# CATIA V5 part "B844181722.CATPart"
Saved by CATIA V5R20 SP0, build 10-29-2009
Part number: B844181722
Revision: 2
Definition: design
Nomenclature: B844181722
Source: made
Description: NOT SPECIFIED
Bounding box of the stored display mesh (mm): x -16.5 to 16.5, y -16.5 to 16.5, z -17 to 22
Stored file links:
  C:\Users\Utente\Desktop\3D files B844\B844181722.CATPart
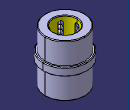
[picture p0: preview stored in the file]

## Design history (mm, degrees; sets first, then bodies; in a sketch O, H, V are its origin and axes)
Body1 "MANIFOLD_SOLID_BREP #38" (main body)
  Solid1: solid without history
Body2 "MANIFOLD_SOLID_BREP #76"
  Solid2: solid without history
Body3 "MANIFOLD_SOLID_BREP #114"
  Solid3: solid without history
Body4 "MANIFOLD_SOLID_BREP #152"
  Solid4: solid without history
Body5 "MANIFOLD_SOLID_BREP #190"
  Solid5: solid without history
Body6 "MANIFOLD_SOLID_BREP #228"
  Solid6: solid without history
Body7 "MANIFOLD_SOLID_BREP #266"
  Solid7: solid without history
Body8 "MANIFOLD_SOLID_BREP #1968"
  Solid8: solid without history
Body9 "MANIFOLD_SOLID_BREP #2006"
  Solid9: solid without history
Body10 "MANIFOLD_SOLID_BREP #2044"
  Solid10: solid without history
Body11 "MANIFOLD_SOLID_BREP #2082"
  Solid11: solid without history
Body12 "MANIFOLD_SOLID_BREP #2120"
  Solid12: solid without history
Body13 "MANIFOLD_SOLID_BREP #2158"
  Solid13: solid without history
Body14 "MANIFOLD_SOLID_BREP #2196"
  Solid14: solid without history
Body15 "MANIFOLD_SOLID_BREP #2234"
  Solid15: solid without history
Body16 "MANIFOLD_SOLID_BREP #2272"
  Solid16: solid without history
Body17 "MANIFOLD_SOLID_BREP #2310"
  Solid17: solid without history
Body18 "MANIFOLD_SOLID_BREP #2348"
  Solid18: solid without history
Body19 "MANIFOLD_SOLID_BREP #2386"
  Solid19: solid without history
Body20 "MANIFOLD_SOLID_BREP #2424"
  Solid20: solid without history
Body21 "MANIFOLD_SOLID_BREP #2462"
  Solid21: solid without history
Body22 "MANIFOLD_SOLID_BREP #2500"
  Solid22: solid without history
Body23 "MANIFOLD_SOLID_BREP #2538"
  Solid23: solid without history
Body24 "MANIFOLD_SOLID_BREP #2576"
  Solid24: solid without history
Body25 "MANIFOLD_SOLID_BREP #2614"
  Solid25: solid without history
Body26 "MANIFOLD_SOLID_BREP #2652"
  Solid26: solid without history
Body27 "MANIFOLD_SOLID_BREP #2690"
  Solid27: solid without history
Body28 "MANIFOLD_SOLID_BREP #2728"
  Solid28: solid without history
Body29 "MANIFOLD_SOLID_BREP #2766"
  Solid29: solid without history
Body30 "MANIFOLD_SOLID_BREP #2804"
  Solid30: solid without history
Body31 "MANIFOLD_SOLID_BREP #2842"
  Solid31: solid without history
Body32 "MANIFOLD_SOLID_BREP #2880"
  Solid32: solid without history
Body33 "MANIFOLD_SOLID_BREP #2918"
  Solid33: solid without history
Body34 "MANIFOLD_SOLID_BREP #2956"
  Solid34: solid without history
Body35 "MANIFOLD_SOLID_BREP #2994"
  Solid35: solid without history
Body36 "MANIFOLD_SOLID_BREP #3032"
  Solid36: solid without history
Body37 "MANIFOLD_SOLID_BREP #3070"
  Solid37: solid without history
Body38 "MANIFOLD_SOLID_BREP #3108"
  Solid38: solid without history
Body39 "MANIFOLD_SOLID_BREP #3146"
  Solid39: solid without history
Body40 "MANIFOLD_SOLID_BREP #3184"
  Solid40: solid without history
Body41 "MANIFOLD_SOLID_BREP #3222"
  Solid41: solid without history
Body42 "MANIFOLD_SOLID_BREP #3260"
  Solid42: solid without history
Body43 "MANIFOLD_SOLID_BREP #3298"
  Solid43: solid without history
Body44 "MANIFOLD_SOLID_BREP #3336"
  Solid44: solid without history
Body45 "MANIFOLD_SOLID_BREP #3374"
  Solid45: solid without history
Body46 "MANIFOLD_SOLID_BREP #3412"
  Solid46: solid without history
Body47 "MANIFOLD_SOLID_BREP #3450"
  Solid47: solid without history
Body48 "MANIFOLD_SOLID_BREP #3488"
  Solid48: solid without history
Body49 "MANIFOLD_SOLID_BREP #3526"
  Solid49: solid without history
Body50 "MANIFOLD_SOLID_BREP #3564"
  Solid50: solid without history
Body51 "MANIFOLD_SOLID_BREP #3602"
  Solid51: solid without history
Body52 "MANIFOLD_SOLID_BREP #3640"
  Solid52: solid without history
Body53 "MANIFOLD_SOLID_BREP #3678"
  Solid53: solid without history
Body54 "MANIFOLD_SOLID_BREP #3716"
  Solid54: solid without history
Body55 "MANIFOLD_SOLID_BREP #3754"
  Solid55: solid without history
Body56 "MANIFOLD_SOLID_BREP #3792"
  Solid56: solid without history
Body57 "MANIFOLD_SOLID_BREP #3830"
  Solid57: solid without history
Body58 "MANIFOLD_SOLID_BREP #3868"
  Solid58: solid without history
Body59 "MANIFOLD_SOLID_BREP #3906"
  Solid59: solid without history
Body60 "MANIFOLD_SOLID_BREP #3944"
  Solid60: solid without history
Body61 "MANIFOLD_SOLID_BREP #3982"
  Solid61: solid without history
